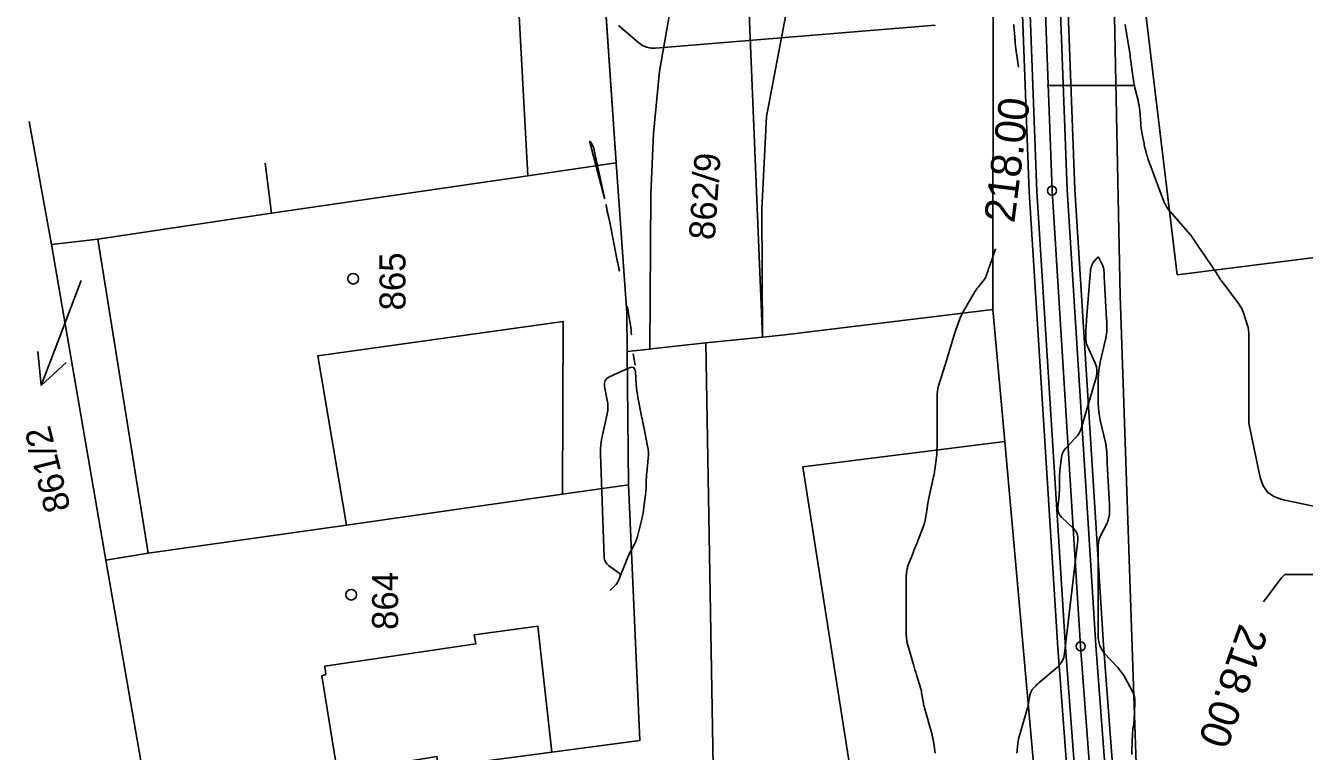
# Model space of a CAD drawing. Extents: x -534481 to -534262, y -1190577 to -1190138.
# Drawn here: x -534378.84 to -534337, y -1190210.64 to -1190186.88 of the extents above; entities that cross this region are included whole.
import ezdxf

# ---------------------------------------------------------------- set-up
doc = ezdxf.new("R2010")
doc.units = 0
for name, color, linetype in [('Bonity', 7, 'Continuous'), ('Definiční body', 7, 'Continuous'), ('Polygon budovy', 7, 'Continuous'), ('Polygon parcely', 7, 'Continuous'), ('Vrstva 17', 7, 'Continuous'), ('Vrstva 18', 7, 'Continuous'), ('Vrstva 19', 7, 'Continuous'), ('Vrstva 35', 7, 'Continuous'), ('Vrstva 37', 7, 'Continuous'), ('Vrstva 46', 7, 'Continuous'), ('Vrstva 47', 7, 'Continuous')]:
    doc.layers.add(name, color=color, linetype=linetype)

msp = doc.modelspace()

# ---------------------------------------------------------------- linework, layer by layer
at = {"layer": 'Bonity'}
msp.add_lwpolyline([(-534342.428, -1190234.65), (-534342.865, -1190226.62), (-534344.323, -1190207.198), (-534345.257, -1190192.285), (-534345.89, -1190175.458), (-534346.05, -1190156.962), (-534344.257, -1190151.926), (-534342.463, -1190149.215)], dxfattribs=at)
at = {"layer": 'Definiční body'}
for p, q in [((-534354.73, -1190197.08), (-534355.5, -1190178.16)), ((-534360.26, -1190180.57), (-534359.52, -1190191.38)), ((-534378.724, -1190190.024), (-534377.99, -1190194.05)), ((-534377.99, -1190194.05), (-534376.48, -1190193.87)), ((-534376.48, -1190193.87), (-534374.83, -1190204.15)), ((-534376.21, -1190204.38), (-534377.99, -1190194.05)), ((-534354.73, -1190197.08), (-534356.58, -1190197.27)), ((-534359.16, -1190197.55), (-534358.42, -1190197.47)), ((-534359.16, -1190197.55), (-534359.11, -1190201.91)), ((-534374.83, -1190204.15), (-534376.21, -1190204.38))]:
    msp.add_line(p, q, dxfattribs=at)
for points in [[(-534349.263, -1190148.015), (-534349.33, -1190148.26), (-534348.67, -1190162.35), (-534348.64, -1190164.35), (-534348.75, -1190166.39), (-534349.02, -1190168.37), (-534349.42, -1190170.33), (-534353.85, -1190185.89), (-534354.6, -1190189.86), (-534354.75, -1190192.89), (-534354.73, -1190197.08)], [(-534347.19, -1190196.18), (-534347.17, -1190176.21), (-534348.39, -1190156.38), (-534345.398, -1190148.697)], [(-534358.42, -1190197.47), (-534358.38, -1190192.4), (-534358.3, -1190190.41), (-534358.1, -1190188.37), (-534357.75, -1190186.39), (-534357.29, -1190184.43), (-534355.5, -1190178.16)], [(-534340.96, -1190232.41), (-534341.05, -1190227.37), (-534341.07, -1190226.16), (-534342.47, -1190212), (-534343.03, -1190195.73), (-534343.24, -1190185.5)], [(-534359.52, -1190191.38), (-534362.41, -1190191.8), (-534370.79, -1190193.02), (-534376.48, -1190193.87)], [(-534359.52, -1190191.38), (-534359.17, -1190196.28), (-534359.16, -1190197.55)], [(-534347.19, -1190196.18), (-534354, -1190197), (-534354.73, -1190197.08)], [(-534347.19, -1190196.18), (-534346.8, -1190200.49), (-534345.1, -1190219.6), (-534344.81, -1190226.96), (-534344.61, -1190231.96)], [(-534356.58, -1190197.27), (-534358.27, -1190197.45), (-534358.42, -1190197.47)], [(-534356.39, -1190231.73), (-534356.2, -1190219.31), (-534356.58, -1190197.27)], [(-534359.11, -1190201.91), (-534361.27, -1190202.22), (-534368.34, -1190203.23), (-534374.83, -1190204.15)], [(-534359.11, -1190201.91), (-534358.74, -1190210.28), (-534361.62, -1190210.66), (-534365.33, -1190211.15), (-534365.38, -1190210.8), (-534368.64, -1190211.34), (-534373.35, -1190212.08)], [(-534376.21, -1190204.38), (-534374.83, -1190212.32), (-534373.35, -1190212.08)]]:
    msp.add_lwpolyline(points, dxfattribs=at)
at = {"layer": 'Polygon parcely'}
for points in [[(-534368.569, -1190186.37), (-534362.74, -1190185.76), (-534362.41, -1190191.8), (-534359.52, -1190191.38), (-534360.26, -1190180.57), (-534364.79, -1190180.95), (-534367.658, -1190181.203)], [(-534378.724, -1190190.024), (-534377.99, -1190194.05), (-534376.48, -1190193.87), (-534370.79, -1190193.02), (-534371.007, -1190191.385)]]:
    msp.add_lwpolyline(points, dxfattribs=at)
for points in [[(-534325.28, -1190183.96), (-534342.24, -1190186.06), (-534341.16, -1190195.04), (-534330.16, -1190193.66), (-534328.97, -1190203.08), (-534323, -1190202.33)], [(-534359.17, -1190196.28), (-534359.52, -1190191.38), (-534362.41, -1190191.8), (-534370.79, -1190193.02), (-534376.48, -1190193.87), (-534374.83, -1190204.15), (-534368.34, -1190203.23), (-534369.28, -1190197.69), (-534361.25, -1190196.57), (-534361.27, -1190202.22), (-534359.11, -1190201.91), (-534359.16, -1190197.55)], [(-534356.39, -1190231.73), (-534347.08, -1190231.91), (-534344.61, -1190231.96), (-534344.81, -1190226.96), (-534345.1, -1190219.6), (-534346.8, -1190200.49), (-534353.41, -1190201.32), (-534350.57, -1190219.42), (-534356.2, -1190219.31)], [(-534374.83, -1190204.15), (-534376.21, -1190204.38), (-534374.83, -1190212.32), (-534373.35, -1190212.08), (-534368.64, -1190211.34), (-534369.15, -1190208.17), (-534369.02, -1190208.12), (-534369.05, -1190207.85), (-534364.11, -1190207.12), (-534364.16, -1190206.82), (-534362.08, -1190206.54), (-534361.62, -1190210.66), (-534358.74, -1190210.28), (-534359.11, -1190201.91), (-534361.27, -1190202.22), (-534368.34, -1190203.23)]]:
    msp.add_lwpolyline(points, close=True, dxfattribs=at)
at = {"layer": 'Vrstva 18'}
for points in [[(-534349.078, -1190186.866), (-534358.236, -1190187.618), (-534358.385, -1190187.617), (-534358.524, -1190187.587), (-534358.654, -1190187.53), (-534358.775, -1190187.444), (-534359.437, -1190186.876)], [(-534346.408, -1190210.691), (-534346.375, -1190210.383), (-534346.365, -1190210.307), (-534346.352, -1190210.231), (-534346.335, -1190210.155), (-534346.315, -1190210.081), (-534346.062, -1190209.214), (-534346.052, -1190209.178), (-534346.043, -1190209.141), (-534346.035, -1190209.105), (-534346.029, -1190209.068), (-534346.003, -1190208.895), (-534345.999, -1190208.87), (-534345.994, -1190208.845), (-534345.988, -1190208.82), (-534345.981, -1190208.796), (-534345.953, -1190208.698), (-534345.944, -1190208.674), (-534345.933, -1190208.652), (-534345.92, -1190208.631), (-534345.904, -1190208.612), (-534345.792, -1190208.49), (-534345.767, -1190208.463), (-534345.741, -1190208.438), (-534345.715, -1190208.414), (-534345.688, -1190208.39), (-534345.094, -1190207.892), (-534344.997, -1190207.795), (-534344.923, -1190207.686), (-534344.872, -1190207.564), (-534344.845, -1190207.43), (-534344.417, -1190203.727), (-534344.416, -1190203.614), (-534344.44, -1190203.51), (-534344.489, -1190203.415), (-534344.563, -1190203.33), (-534344.949, -1190202.97), (-534345.006, -1190202.903), (-534345.045, -1190202.83), (-534345.065, -1190202.75), (-534345.066, -1190202.662), (-534345.026, -1190202.25), (-534345.021, -1190202.182), (-534345.017, -1190202.115), (-534345.014, -1190202.047), (-534345.014, -1190201.98), (-534345.014, -1190201.709), (-534345.013, -1190201.642), (-534345.01, -1190201.574), (-534345.005, -1190201.507), (-534344.998, -1190201.44), (-534344.95, -1190201.027), (-534344.932, -1190200.939), (-534344.902, -1190200.857), (-534344.859, -1190200.781), (-534344.802, -1190200.712), (-534344.495, -1190200.389), (-534344.428, -1190200.31), (-534344.372, -1190200.225), (-534344.326, -1190200.134), (-534344.291, -1190200.036), (-534343.813, -1190198.403), (-534343.789, -1190198.284), (-534343.786, -1190198.166), (-534343.805, -1190198.051), (-534343.846, -1190197.936), (-534344.111, -1190197.348), (-534344.129, -1190197.3), (-534344.142, -1190197.252), (-534344.15, -1190197.202), (-534344.153, -1190197.152), (-534344.153, -1190196.94), (-534344.153, -1190196.892), (-534344.151, -1190196.845), (-534344.149, -1190196.797), (-534344.145, -1190196.75), (-534344.127, -1190196.512), (-534344.115, -1190196.37), (-534344.018, -1190195.15), (-534344.009, -1190195.048), (-534343.997, -1190194.894), (-534343.994, -1190194.869), (-534343.99, -1190194.845), (-534343.984, -1190194.821), (-534343.977, -1190194.798), (-534343.945, -1190194.705), (-534343.936, -1190194.682), (-534343.925, -1190194.661), (-534343.912, -1190194.64), (-534343.898, -1190194.621), (-534343.79, -1190194.491), (-534343.767, -1190194.47), (-534343.747, -1190194.465), (-534343.728, -1190194.475), (-534343.712, -1190194.501), (-534343.626, -1190194.68), (-534343.619, -1190194.696), (-534343.611, -1190194.712), (-534343.605, -1190194.729), (-534343.598, -1190194.745), (-534343.573, -1190194.811), (-534343.568, -1190194.828), (-534343.564, -1190194.845), (-534343.561, -1190194.862), (-534343.56, -1190194.88), (-534343.556, -1190194.986), (-534343.555, -1190195.009), (-534343.554, -1190195.033), (-534343.553, -1190195.056), (-534343.552, -1190195.08), (-534343.471, -1190196.5), (-534343.469, -1190196.534), (-534343.468, -1190196.569), (-534343.466, -1190196.603), (-534343.465, -1190196.638), (-534343.461, -1190196.781), (-534343.46, -1190196.813), (-534343.461, -1190196.844), (-534343.463, -1190196.876), (-534343.467, -1190196.908), (-534343.482, -1190197.034), (-534343.486, -1190197.066), (-534343.492, -1190197.097), (-534343.498, -1190197.129), (-534343.505, -1190197.16), (-534343.68, -1190197.897), (-534343.707, -1190198.031), (-534343.727, -1190198.165), (-534343.739, -1190198.301), (-534343.743, -1190198.437), (-534343.743, -1190199.254), (-534343.739, -1190199.391), (-534343.727, -1190199.526), (-534343.708, -1190199.661), (-534343.68, -1190199.794), (-534343.506, -1190200.532), (-534343.5, -1190200.563), (-534343.494, -1190200.594), (-534343.489, -1190200.625), (-534343.484, -1190200.656), (-534343.47, -1190200.782), (-534343.466, -1190200.813), (-534343.463, -1190200.845), (-534343.461, -1190200.876), (-534343.46, -1190200.908), (-534343.455, -1190201.062), (-534343.454, -1190201.098), (-534343.453, -1190201.135), (-534343.451, -1190201.171), (-534343.449, -1190201.207), (-534343.385, -1190202.391), (-534343.383, -1190202.436), (-534343.381, -1190202.482), (-534343.379, -1190202.527), (-534343.377, -1190202.572), (-534343.372, -1190202.767), (-534343.372, -1190202.806), (-534343.374, -1190202.844), (-534343.379, -1190202.882), (-534343.387, -1190202.92), (-534343.423, -1190203.071), (-534343.433, -1190203.108), (-534343.445, -1190203.145), (-534343.46, -1190203.181), (-534343.477, -1190203.215), (-534343.668, -1190203.582), (-534343.701, -1190203.655), (-534343.724, -1190203.731), (-534343.738, -1190203.81), (-534343.743, -1190203.89), (-534343.743, -1190206.916), (-534343.731, -1190207.056), (-534343.694, -1190207.186), (-534343.633, -1190207.307), (-534343.547, -1190207.419), (-534343.108, -1190207.895), (-534343.035, -1190207.979), (-534342.969, -1190208.067), (-534342.907, -1190208.159), (-534342.852, -1190208.255), (-534342.635, -1190208.661), (-534342.592, -1190208.754), (-534342.563, -1190208.851), (-534342.548, -1190208.95), (-534342.546, -1190209.052), (-534342.571, -1190209.602), (-534342.573, -1190209.639), (-534342.576, -1190209.676), (-534342.581, -1190209.712), (-534342.586, -1190209.749), (-534342.609, -1190209.894), (-534342.614, -1190209.931), (-534342.618, -1190209.967), (-534342.621, -1190210.004), (-534342.623, -1190210.041), (-534342.644, -1190210.625), (-534342.651, -1190210.734)]]:
    msp.add_lwpolyline(points, dxfattribs=at)
at = {"layer": 'Vrstva 19'}
for points in [[(-534346.351, -1190188.242), (-534346.351, -1190188.239), (-534346.361, -1190188.163), (-534346.372, -1190188.088), (-534346.427, -1190187.725), (-534346.439, -1190187.64), (-534346.45, -1190187.554), (-534346.46, -1190187.468), (-534346.468, -1190187.382), (-534346.499, -1190187.022), (-534346.506, -1190186.933), (-534346.512, -1190186.844)], [(-534342.862, -1190186.844), (-534342.85, -1190186.951), (-534342.833, -1190187.058), (-534342.707, -1190187.785), (-534342.706, -1190187.795), (-534342.704, -1190187.805), (-534342.703, -1190187.815), (-534342.703, -1190187.826), (-534342.701, -1190187.867), (-534342.701, -1190187.877), (-534342.7, -1190187.887), (-534342.699, -1190187.897), (-534342.697, -1190187.908), (-534342.591, -1190188.676), (-534342.578, -1190188.76), (-534342.563, -1190188.844), (-534342.546, -1190188.927), (-534342.526, -1190189.009), (-534342.443, -1190189.338), (-534342.424, -1190189.421), (-534342.408, -1190189.504), (-534342.396, -1190189.587), (-534342.388, -1190189.672), (-534342.356, -1190190.091), (-534342.349, -1190190.167), (-534342.34, -1190190.243), (-534342.329, -1190190.319), (-534342.315, -1190190.394), (-534342.248, -1190190.747), (-534342.238, -1190190.796), (-534342.227, -1190190.844), (-534342.216, -1190190.892), (-534342.203, -1190190.94), (-534342.151, -1190191.131), (-534342.138, -1190191.179), (-534342.123, -1190191.226), (-534342.107, -1190191.273), (-534342.091, -1190191.32), (-534341.596, -1190192.638), (-534341.587, -1190192.659), (-534341.579, -1190192.681), (-534341.569, -1190192.701), (-534341.559, -1190192.722), (-534341.517, -1190192.804), (-534341.506, -1190192.824), (-534341.494, -1190192.843), (-534341.481, -1190192.861), (-534341.466, -1190192.879), (-534340.749, -1190193.707), (-534340.716, -1190193.746), (-534340.685, -1190193.786), (-534340.656, -1190193.827), (-534340.627, -1190193.869), (-534340.517, -1190194.04), (-534340.49, -1190194.083), (-534340.462, -1190194.125), (-534340.433, -1190194.167), (-534340.405, -1190194.209), (-534340.031, -1190194.757), (-534340.001, -1190194.801), (-534339.972, -1190194.845), (-534339.943, -1190194.889), (-534339.914, -1190194.933), (-534339.8, -1190195.111), (-534339.771, -1190195.156), (-534339.742, -1190195.199), (-534339.711, -1190195.242), (-534339.68, -1190195.285), (-534339.149, -1190195.992), (-534339.097, -1190196.067), (-534339.052, -1190196.147), (-534339.014, -1190196.23), (-534338.982, -1190196.316), (-534338.869, -1190196.668), (-534338.845, -1190196.757), (-534338.827, -1190196.847), (-534338.817, -1190196.938), (-534338.813, -1190197.029), (-534338.813, -1190197.792), (-534338.813, -1190197.95), (-534338.813, -1190198.612), (-534338.813, -1190198.845), (-534338.813, -1190199.077), (-534338.813, -1190199.792), (-534338.813, -1190199.88), (-534338.813, -1190199.897), (-534338.811, -1190199.914), (-534338.809, -1190199.932), (-534338.806, -1190199.949), (-534338.445, -1190201.678), (-534338.354, -1190201.943), (-534338.206, -1190202.15), (-534337.999, -1190202.299), (-534337.735, -1190202.39), (-534332.013, -1190203.605)], [(-534345.417, -1190188.845), (-534342.568, -1190188.845)], [(-534349.076, -1190210.694), (-534349.119, -1190210.393), (-534349.131, -1190210.318), (-534349.146, -1190210.243), (-534349.163, -1190210.169), (-534349.182, -1190210.096), (-534349.431, -1190209.208), (-534349.441, -1190209.172), (-534349.45, -1190209.136), (-534349.458, -1190209.1), (-534349.465, -1190209.063), (-534349.495, -1190208.896), (-534349.5, -1190208.87), (-534349.504, -1190208.844), (-534349.508, -1190208.819), (-534349.513, -1190208.793), (-534349.528, -1190208.689), (-534349.533, -1190208.664), (-534349.538, -1190208.638), (-534349.544, -1190208.613), (-534349.552, -1190208.588), (-534349.691, -1190208.133), (-534349.717, -1190208.049), (-534349.742, -1190207.965), (-534349.767, -1190207.881), (-534349.792, -1190207.796), (-534349.977, -1190207.157), (-534349.985, -1190207.126), (-534349.992, -1190207.096), (-534349.998, -1190207.065), (-534350.003, -1190207.033), (-534350.019, -1190206.907), (-534350.022, -1190206.876), (-534350.025, -1190206.844), (-534350.026, -1190206.813), (-534350.027, -1190206.781), (-534350.027, -1190204.906), (-534350.026, -1190204.875), (-534350.024, -1190204.845), (-534350.021, -1190204.814), (-534350.016, -1190204.784), (-534349.996, -1190204.662), (-534349.991, -1190204.632), (-534349.983, -1190204.602), (-534349.974, -1190204.573), (-534349.964, -1190204.544), (-534349.804, -1190204.14), (-534349.774, -1190204.063), (-534349.743, -1190203.986), (-534349.713, -1190203.909), (-534349.684, -1190203.832), (-534349.455, -1190203.237), (-534349.441, -1190203.2), (-534349.429, -1190203.161), (-534349.419, -1190203.122), (-534349.411, -1190203.083), (-534349.381, -1190202.924), (-534349.374, -1190202.884), (-534349.367, -1190202.844), (-534349.361, -1190202.804), (-534349.355, -1190202.765), (-534349.319, -1190202.515), (-534349.311, -1190202.46), (-534349.301, -1190202.405), (-534349.29, -1190202.351), (-534349.279, -1190202.297), (-534349.132, -1190201.651), (-534349.115, -1190201.572), (-534349.1, -1190201.492), (-534349.087, -1190201.411), (-534349.076, -1190201.33), (-534349.038, -1190201.006), (-534349.03, -1190200.925), (-534349.024, -1190200.844), (-534349.021, -1190200.763), (-534349.019, -1190200.681), (-534349.019, -1190200.19), (-534349.019, -1190199.983), (-534349.019, -1190199.637), (-534349.019, -1190199.43), (-534349.019, -1190199.025), (-534349.016, -1190198.935), (-534349.006, -1190198.846), (-534348.99, -1190198.758), (-534348.967, -1190198.671), (-534348.758, -1190197.989), (-534348.646, -1190197.622), (-534348.447, -1190196.968), (-534348.427, -1190196.907), (-534348.407, -1190196.845), (-534348.386, -1190196.784), (-534348.364, -1190196.723), (-534348.274, -1190196.48), (-534348.25, -1190196.42), (-534348.224, -1190196.361), (-534348.195, -1190196.303), (-534348.164, -1190196.247), (-534347.804, -1190195.63), (-534347.773, -1190195.579), (-534347.739, -1190195.528), (-534347.704, -1190195.48), (-534347.666, -1190195.432), (-534347.488, -1190195.214), (-534347.463, -1190195.182), (-534347.443, -1190195.148), (-534347.425, -1190195.112), (-534347.41, -1190195.075), (-534347.358, -1190194.921), (-534347.345, -1190194.883), (-534347.332, -1190194.845), (-534347.319, -1190194.806), (-534347.306, -1190194.768), (-534347.163, -1190194.351), (-534347.139, -1190194.285), (-534347.113, -1190194.22), (-534347.103, -1190194.195)], [(-534358.967, -1190197.621), (-534358.901, -1190198.002)], [(-534332.537, -1190204.845), (-534337.626, -1190204.845), (-534337.634, -1190204.845), (-534337.642, -1190204.848), (-534337.649, -1190204.852), (-534337.655, -1190204.858), (-534337.678, -1190204.885), (-534337.69, -1190204.898), (-534337.702, -1190204.911), (-534337.73, -1190204.94), (-534337.736, -1190204.947), (-534337.743, -1190204.955), (-534337.749, -1190204.962), (-534337.755, -1190204.97), (-534338.34, -1190205.741)]]:
    msp.add_lwpolyline(points, dxfattribs=at)
for points in [[(-534360.382, -1190190.677), (-534360.38, -1190190.668), (-534360.373, -1190190.673), (-534360.359, -1190190.692), (-534360.294, -1190190.794), (-534360.279, -1190190.82), (-534360.266, -1190190.847), (-534360.256, -1190190.875), (-534360.248, -1190190.904), (-534360.158, -1190191.324), (-534359.931, -1190192.369), (-534359.903, -1190192.507), (-534359.895, -1190192.553), (-534359.91, -1190192.508), (-534359.946, -1190192.372), (-534360.377, -1190190.7)], [(-534359.433, -1190194.812), (-534359.44, -1190194.779), (-534359.467, -1190194.648), (-534359.474, -1190194.615), (-534359.481, -1190194.582), (-534359.487, -1190194.55), (-534359.494, -1190194.517), (-534359.728, -1190193.318), (-534359.736, -1190193.278), (-534359.744, -1190193.239), (-534359.753, -1190193.199), (-534359.762, -1190193.159), (-534359.816, -1190192.941), (-534359.818, -1190192.931), (-534359.82, -1190192.922), (-534359.821, -1190192.912), (-534359.822, -1190192.902), (-534359.827, -1190192.864), (-534359.828, -1190192.854), (-534359.829, -1190192.845), (-534359.831, -1190192.835), (-534359.833, -1190192.826), (-534359.846, -1190192.763), (-534359.849, -1190192.752), (-534359.85, -1190192.749), (-534359.849, -1190192.752), (-534359.848, -1190192.763), (-534359.828, -1190192.875), (-534359.824, -1190192.898), (-534359.82, -1190192.922), (-534359.815, -1190192.945), (-534359.809, -1190192.968), (-534359.762, -1190193.159), (-534359.753, -1190193.199), (-534359.744, -1190193.239), (-534359.736, -1190193.278), (-534359.728, -1190193.318), (-534359.494, -1190194.517), (-534359.487, -1190194.55), (-534359.481, -1190194.582), (-534359.474, -1190194.615), (-534359.467, -1190194.648), (-534359.44, -1190194.779), (-534359.433, -1190194.812), (-534359.427, -1190194.845)], [(-534359.42, -1190194.877), (-534359.414, -1190194.91), (-534359.42, -1190194.877), (-534359.427, -1190194.845)], [(-534359.042, -1190196.767), (-534359.053, -1190196.689), (-534359.099, -1190196.379), (-534359.112, -1190196.302), (-534359.126, -1190196.225), (-534359.141, -1190196.148), (-534359.159, -1190196.071), (-534359.141, -1190196.148), (-534359.126, -1190196.225), (-534359.112, -1190196.302), (-534359.099, -1190196.379), (-534359.053, -1190196.689), (-534359.042, -1190196.767), (-534359.032, -1190196.845)], [(-534359.024, -1190196.923), (-534359.017, -1190197.001), (-534359.024, -1190196.923), (-534359.032, -1190196.845)], [(-534359.521, -1190205.171), (-534359.497, -1190205.143), (-534359.476, -1190205.114), (-534359.458, -1190205.083), (-534359.443, -1190205.05), (-534359.391, -1190204.913), (-534359.383, -1190204.88), (-534359.386, -1190204.851), (-534359.399, -1190204.825), (-534359.424, -1190204.802), (-534359.767, -1190204.553), (-534359.826, -1190204.501), (-534359.869, -1190204.439), (-534359.896, -1190204.369), (-534359.907, -1190204.291), (-534360.027, -1190200.91), (-534360.028, -1190200.753), (-534360.019, -1190200.597), (-534359.999, -1190200.442), (-534359.97, -1190200.288), (-534359.813, -1190199.587), (-534359.793, -1190199.476), (-534359.786, -1190199.364), (-534359.791, -1190199.253), (-534359.807, -1190199.141), (-534359.895, -1190198.693), (-534359.901, -1190198.59), (-534359.876, -1190198.502), (-534359.819, -1190198.431), (-534359.731, -1190198.376), (-534359.093, -1190198.089), (-534359.008, -1190198.064), (-534358.946, -1190198.077), (-534358.905, -1190198.126), (-534358.887, -1190198.213), (-534358.859, -1190198.634), (-534358.85, -1190198.739), (-534358.838, -1190198.844), (-534358.823, -1190198.948), (-534358.805, -1190199.052), (-534358.675, -1190199.717), (-534358.67, -1190199.742), (-534358.665, -1190199.767), (-534358.66, -1190199.791), (-534358.655, -1190199.816), (-534358.635, -1190199.914), (-534358.63, -1190199.938), (-534358.625, -1190199.963), (-534358.62, -1190199.987), (-534358.615, -1190200.012), (-534358.488, -1190200.651), (-534358.472, -1190200.748), (-534358.464, -1190200.845), (-534358.463, -1190200.943), (-534358.469, -1190201.041), (-534358.518, -1190201.525), (-534358.523, -1190201.578), (-534358.526, -1190201.63), (-534358.529, -1190201.683), (-534358.531, -1190201.735), (-534358.535, -1190201.946), (-534358.537, -1190201.998), (-534358.54, -1190202.051), (-534358.544, -1190202.103), (-534358.549, -1190202.155), (-534358.609, -1190202.646), (-534358.622, -1190202.745), (-534358.638, -1190202.843), (-534358.658, -1190202.941), (-534358.68, -1190203.039), (-534358.819, -1190203.605), (-534358.837, -1190203.67), (-534358.859, -1190203.733), (-534358.886, -1190203.795), (-534358.916, -1190203.855), (-534359.046, -1190204.093), (-534359.077, -1190204.153), (-534359.107, -1190204.214), (-534359.135, -1190204.275), (-534359.161, -1190204.338), (-534359.337, -1190204.776), (-534359.351, -1190204.811), (-534359.364, -1190204.845), (-534359.377, -1190204.879), (-534359.391, -1190204.913), (-534359.443, -1190205.05), (-534359.458, -1190205.083), (-534359.476, -1190205.114), (-534359.497, -1190205.143), (-534359.521, -1190205.171), (-534359.709, -1190205.362)]]:
    msp.add_lwpolyline(points, close=True, dxfattribs=at)
at = {"layer": 'Vrstva 35'}
for points in [[(-534343.317, -1190232.109), (-534343.613, -1190226.668), (-534345.072, -1190207.25), (-534346.006, -1190192.323), (-534346.64, -1190175.475), (-534346.801, -1190156.835), (-534344.933, -1190151.588), (-534343.268, -1190149.073)], [(-534343.067, -1190232.098), (-534343.364, -1190226.652), (-534344.822, -1190207.233), (-534345.756, -1190192.31), (-534346.39, -1190175.47), (-534346.551, -1190156.878), (-534344.708, -1190151.701), (-534343, -1190149.12)], [(-534342.068, -1190232.057), (-534342.366, -1190226.587), (-534343.825, -1190207.164), (-534344.757, -1190192.26), (-534345.39, -1190175.446), (-534345.55, -1190157.046), (-534343.807, -1190152.151), (-534341.926, -1190149.309)], [(-534341.818, -1190232.046), (-534342.116, -1190226.571), (-534343.575, -1190207.147), (-534344.507, -1190192.248), (-534345.14, -1190175.441), (-534345.299, -1190157.088), (-534343.581, -1190152.264), (-534341.657, -1190149.357)]]:
    msp.add_lwpolyline(points, dxfattribs=at)
at = {"layer": 'Vrstva 37'}
for centre in [(-534345.257, -1190192.285), (-534345.257, -1190192.285), (-534345.257, -1190192.285), (-534345.257, -1190192.285), (-534345.257, -1190192.285), (-534345.257, -1190192.285), (-534344.323, -1190207.198), (-534344.323, -1190207.198), (-534344.323, -1190207.198), (-534344.323, -1190207.198), (-534344.323, -1190207.198), (-534344.323, -1190207.198)]:
    msp.add_circle(centre, 0.15, dxfattribs=at)
at = {"layer": 'Vrstva 46'}
for centre in [(-534368.124, -1190195.168), (-534368.188, -1190205.51)]:
    msp.add_circle(centre, 0.175, dxfattribs=at)
at = {"layer": 'Vrstva 47'}
for p, q in [((-534377.02, -1190195.23), (-534377.26, -1190195.86)), ((-534377.26, -1190195.86), (-534378.335, -1190198.662)), ((-534378.335, -1190198.662), (-534378.444, -1190197.547)), ((-534378.335, -1190198.662), (-534377.509, -1190197.906))]:
    msp.add_line(p, q, dxfattribs=at)

# ---------------------------------------------------------------- texts
at = {"layer": 'Polygon budovy'}
for s, rotation, p in [('862/9', 86, (-534356.294, -1190193.919)), ('865', 90, (-534366.411, -1190196.205)), ('861/2', 104, (-534377.363, -1190202.695)), ('864', 90, (-534366.653, -1190206.662))]:
    msp.add_text(s, height=0.85, rotation=rotation, dxfattribs=at).set_placement(p)
at = {"layer": 'Vrstva 17'}
for rotation, p in [(82.8047, (-534346.492, -1190193.367)), (250.4804, (-534339.112, -1190206.42))]:
    msp.add_text('218.00', height=1, rotation=rotation, dxfattribs=at).set_placement(p)

doc.saveas('drawing.dxf')
